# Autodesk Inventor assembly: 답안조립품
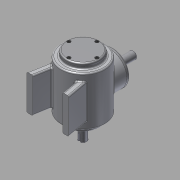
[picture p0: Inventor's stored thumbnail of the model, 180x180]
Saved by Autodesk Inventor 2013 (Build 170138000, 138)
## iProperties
Created: 2015-01
Part Number: 답안조립품
Document SubType Name: Assembly
Designer: Administrator
Author: Administrator
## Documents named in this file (15)
- C:\Users\Administrator\Desktop\450106V1003\답안조립품.iam
- C:\Users\Administrator\Desktop\450106V1003\본체.ipt
- C:\Users\Administrator\Desktop\450106V1003\서브 축.ipt
- 서브 축.ipt
- C:\Users\Administrator\Desktop\450106V1003\키 4x4.ipt
- C:\Users\Administrator\Desktop\450106V1003\커버.ipt
- C:\Users\Administrator\Desktop\450106V1003\베어링 6203.ipt
- C:\Users\Administrator\Desktop\450106V1003\오일실.ipt
- C:\Users\Administrator\Desktop\450106V1003\서브 베벨기어.ipt
- C:\Users\Administrator\Desktop\450106V1003\메인 축.ipt
- 메인 축.ipt
- C:\Users\Administrator\Desktop\450106V1003\키 5x5.ipt
- C:\Users\Administrator\Desktop\450106V1003\메인 베벨기어.ipt
- C:\Users\Administrator\Desktop\450106V1003\커버2.ipt
- C:\Users\Administrator\Desktop\450106V1003\M4.ipt
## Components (12 placed, 1 different names)
1. M4:1
2. M4:2
3. M4:3
4. M4:4
5. M4:5
6. M4:6
7. M4:7
8. M4:8
9. M4:9
10. M4:10
11. M4:11
12. M4:12
